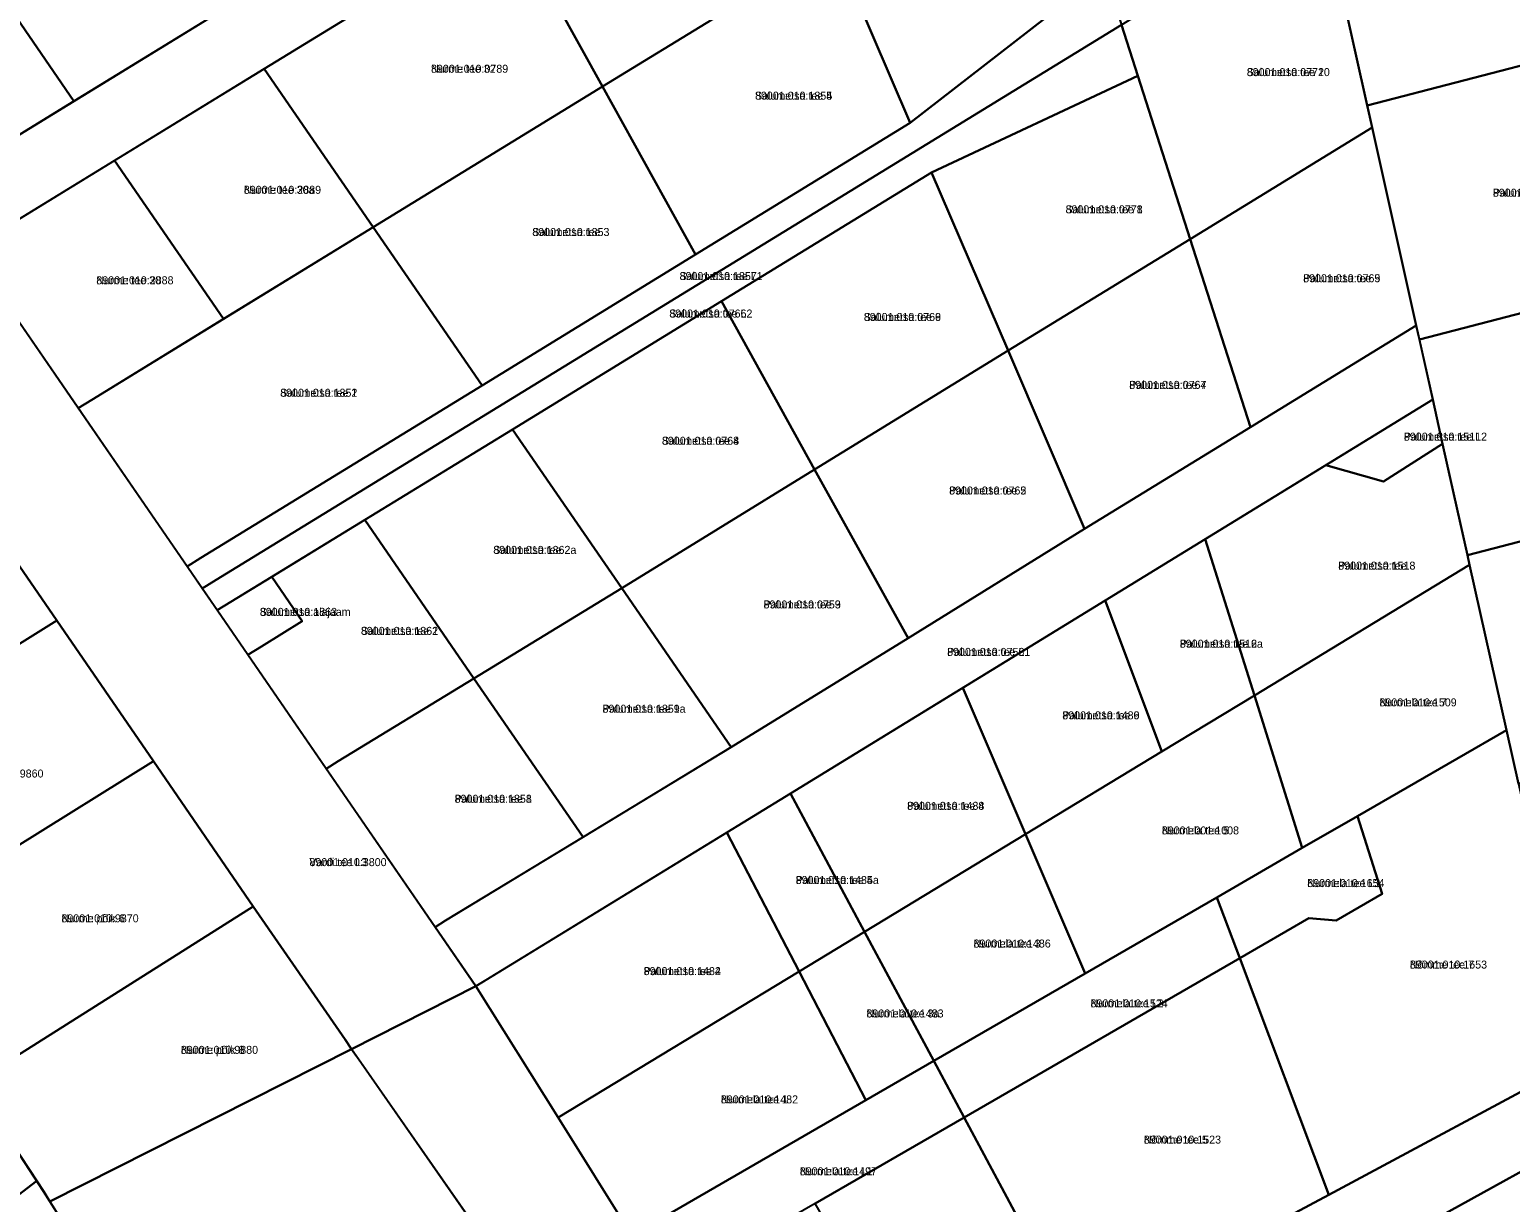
# Model space of a CAD drawing. Extents: x 526849 to 562296, y 6591741 to 6618546.
# Drawn here: x 546246.1 to 546524.3, y 6598599.5 to 6598819.9 of the extents above; entities that cross this region are included whole.
import ezdxf

# ---------------------------------------------------------------- set-up
doc = ezdxf.new("R2010")
doc.units = 0
for name, color, linetype in [('L_AADRESS', 7, 'Continuous'), ('PIIR', 7, 'Continuous'), ('TUNNUS', 7, 'Continuous')]:
    doc.layers.add(name, color=color, linetype=linetype)

msp = doc.modelspace()

# ---------------------------------------------------------------- linework, layer by layer
at = {"layer": 'PIIR'}
for points in [[(546227.01, 6598789.61), (546229.57, 6598791.18), (546282.53, 6598823.65), (546327.15, 6598851.02), (546371.97, 6598878.5), (546413.8, 6598904.15), (546446.52, 6598936.13), (546471.16, 6598923.58), (546475.1, 6598905.89), (546459.53, 6598913.79), (546427, 6598896.41), (546382.82, 6598869.32), (546336.26, 6598840.76), (546290.19, 6598812.52), (546237.29, 6598780.08), (546234.73, 6598778.51), (546230.83, 6598784.18)], [(546382.82, 6598869.32), (546397.2, 6598835.82), (546353.75, 6598809.17), (546336.26, 6598840.76)], [(546397.2, 6598835.82), (546438.34, 6598861.05), (546448.06, 6598830.75), (546411.59, 6598802.33)], [(546487.88, 6598848.56), (546523.89, 6598857.91), (546525.06, 6598853.05), (546534.16, 6598815.11), (546497.46, 6598805.58), (546488.92, 6598843.88)], [(546232.91, 6598837.74), (546260.42, 6598855.23), (546282.53, 6598823.65), (546254.4, 6598806.4)], [(546451.25, 6598820.78), (546488.92, 6598843.88), (546498.37, 6598801.48), (546464.17, 6598780.51), (546454.34, 6598811.15)], [(546290.19, 6598812.52), (546336.26, 6598840.76), (546353.75, 6598809.17), (546310.66, 6598782.75)], [(546205.45, 6598820.29), (546207.99, 6598821.9), (546232.91, 6598837.74), (546254.4, 6598806.4), (546229.57, 6598791.18), (546227.01, 6598789.61)], [(546353.75, 6598809.17), (546397.2, 6598835.82), (546411.59, 6598802.33), (546371.23, 6598777.58)], [(546275.68, 6598718.99), (546278.28, 6598720.58), (546331.14, 6598752.99), (546371.23, 6598777.58), (546411.59, 6598802.33), (546448.06, 6598830.75), (546451.25, 6598820.78), (546281.13, 6598716.46), (546278.52, 6598714.86)], [(546278.52, 6598714.86), (546281.13, 6598716.46), (546451.25, 6598820.78), (546454.34, 6598811.15), (546415.57, 6598793.04), (546376.08, 6598768.82), (546336.81, 6598744.74), (546283.93, 6598712.31), (546281.35, 6598710.73)], [(546497.46, 6598805.58), (546534.16, 6598815.11), (546543.5, 6598776.21), (546544.67, 6598771.35), (546507.25, 6598761.63), (546506.66, 6598764.26), (546498.37, 6598801.48)], [(546262.06, 6598795.27), (546290.19, 6598812.52), (546310.66, 6598782.75), (546282.53, 6598765.5)], [(546415.57, 6598793.04), (546454.34, 6598811.15), (546464.17, 6598780.51), (546429.96, 6598759.54)], [(546310.66, 6598782.75), (546353.75, 6598809.17), (546371.23, 6598777.58), (546331.14, 6598752.99)], [(546464.17, 6598780.51), (546498.37, 6598801.48), (546506.66, 6598764.26), (546475.5, 6598745.16)], [(546234.73, 6598778.51), (546237.29, 6598780.08), (546262.06, 6598795.27), (546282.53, 6598765.5), (546257.76, 6598750.31), (546255.2, 6598748.75)], [(546376.08, 6598768.82), (546415.57, 6598793.04), (546429.96, 6598759.54), (546393.6, 6598737.17)], [(546255.2, 6598748.75), (546257.76, 6598750.31), (546310.66, 6598782.75), (546331.14, 6598752.99), (546278.28, 6598720.58), (546275.68, 6598718.99)], [(546429.96, 6598759.54), (546464.17, 6598780.51), (546475.5, 6598745.16), (546444.34, 6598726.05)], [(546507.25, 6598761.63), (546544.67, 6598771.35), (546545.83, 6598766.48), (546554.35, 6598730.98), (546516.28, 6598721.1), (546514.43, 6598729.4), (546511.62, 6598742.01), (546509.77, 6598750.33)], [(546336.81, 6598744.74), (546376.08, 6598768.82), (546393.6, 6598737.17), (546357.36, 6598714.87)], [(546322.3, 6598651.21), (546324.27, 6598652.41), (546377.91, 6598685), (546411.16, 6598705.47), (546444.34, 6598726.05), (546475.5, 6598745.16), (546506.66, 6598764.26), (546509.77, 6598750.33), (546448.21, 6598712.58), (546389.08, 6598676.33), (546331.81, 6598641.21), (546329.96, 6598640.07)], [(546393.6, 6598737.17), (546429.96, 6598759.54), (546444.34, 6598726.05), (546411.16, 6598705.47)], [(546489.66, 6598738), (546509.77, 6598750.33), (546511.62, 6598742.01), (546500.53, 6598734.92)], [(546309.08, 6598727.74), (546336.81, 6598744.74), (546357.36, 6598714.87), (546329.59, 6598697.92)], [(546467, 6598724.11), (546489.66, 6598738), (546500.53, 6598734.92), (546511.62, 6598742.01), (546516.28, 6598721.1), (546516.68, 6598719.28), (546476.24, 6598694.75)], [(546357.36, 6598714.87), (546393.6, 6598737.17), (546411.16, 6598705.47), (546377.91, 6598685)], [(546201.21, 6598715.36), (546204.6, 6598717.48), (546232.99, 6598735.27), (546251.19, 6598708.83), (546218.96, 6598688.7)], [(546516.28, 6598721.1), (546554.35, 6598730.98), (546563.46, 6598693.05), (546564.62, 6598688.19), (546525.85, 6598678.12), (546523.6, 6598688.23), (546516.68, 6598719.28)], [(546287.11, 6598702.36), (546289.66, 6598703.94), (546297.33, 6598708.68), (546291.6, 6598717.02), (546309.08, 6598727.74), (546329.59, 6598697.92), (546304.1, 6598682.36), (546301.83, 6598680.97)], [(546448.21, 6598712.58), (546467, 6598724.11), (546476.24, 6598694.75), (546458.87, 6598684.21)], [(546476.24, 6598694.75), (546516.68, 6598719.28), (546523.6, 6598688.23), (546495.64, 6598672.07), (546485.25, 6598666.08)], [(546281.35, 6598710.73), (546283.93, 6598712.31), (546291.6, 6598717.02), (546297.33, 6598708.68), (546289.66, 6598703.94), (546287.11, 6598702.36)], [(546329.59, 6598697.92), (546357.36, 6598714.87), (546377.91, 6598685), (546350.1, 6598668.1)], [(546421.44, 6598696.16), (546448.21, 6598712.58), (546458.87, 6598684.21), (546433.22, 6598668.66)], [(546199.52, 6598676.55), (546251.19, 6598708.83), (546269.38, 6598682.37), (546217.07, 6598649.79)], [(546301.83, 6598680.97), (546304.1, 6598682.36), (546329.59, 6598697.92), (546350.1, 6598668.1), (546324.27, 6598652.41), (546322.3, 6598651.21)], [(546389.08, 6598676.33), (546421.44, 6598696.16), (546433.22, 6598668.66), (546403, 6598650.33)], [(546469.18, 6598656.79), (546444.44, 6598642.48), (546433.22, 6598668.66), (546458.87, 6598684.21), (546476.24, 6598694.75), (546485.25, 6598666.08)], [(546473.49, 6598645.37), (546486.48, 6598652.9), (546491.6, 6598652.43), (546500.25, 6598657.44), (546495.64, 6598672.07), (546523.6, 6598688.23), (546525.85, 6598678.12), (546537.42, 6598626.18), (546490.21, 6598600.91)], [(546217.07, 6598649.79), (546269.38, 6598682.37), (546288.13, 6598655.1), (546235.42, 6598621.83)], [(546377.09, 6598668.97), (546389.08, 6598676.33), (546403, 6598650.33), (546390.68, 6598642.86)], [(546469.18, 6598656.79), (546485.25, 6598666.08), (546495.64, 6598672.07), (546500.25, 6598657.44), (546491.6, 6598652.43), (546486.48, 6598652.9), (546473.49, 6598645.37)], [(546329.96, 6598640.07), (546377.09, 6598668.97), (546390.68, 6598642.86), (546345.4, 6598615.39)], [(546403, 6598650.33), (546433.22, 6598668.66), (546444.44, 6598642.48), (546416.01, 6598626.06)], [(546416.01, 6598626.06), (546444.44, 6598642.48), (546469.18, 6598656.79), (546473.49, 6598645.37), (546421.69, 6598615.44)], [(546248.72, 6598601.48), (546235.42, 6598621.83), (546288.13, 6598655.1), (546305.36, 6598630.05), (546306.59, 6598628.27), (546249.9, 6598599.66)], [(546390.68, 6598642.86), (546403, 6598650.33), (546416.01, 6598626.06), (546403.25, 6598618.69)], [(546421.69, 6598615.44), (546473.49, 6598645.37), (546490.21, 6598600.91), (546443.01, 6598575.64)], [(546345.4, 6598615.39), (546390.68, 6598642.86), (546403.25, 6598618.69), (546359.25, 6598593.27)], [(546249.9, 6598599.66), (546306.59, 6598628.27), (546308.31, 6598625.81), (546330.28, 6598594.29), (546276.64, 6598565.37), (546272.94, 6598563.37), (546264.35, 6598576.9)], [(546359.25, 6598593.27), (546403.25, 6598618.69), (546416.01, 6598626.06), (546421.69, 6598615.44), (546393.69, 6598599.27), (546370.98, 6598586.14), (546365.64, 6598583.06)], [(546195.44, 6598591.91), (546235.39, 6598621.82), (546247.42, 6598603.5), (546207.88, 6598573.16)], [(546393.69, 6598599.27), (546421.69, 6598615.44), (546443.01, 6598575.64), (546415.78, 6598561.05)], [(546508.58, 6598595.44), (546540.36, 6598613), (546543.44, 6598599.17)], [(546207.88, 6598573.16), (546247.42, 6598603.5), (546248.74, 6598601.5), (546249.9, 6598599.66), (546259.24, 6598584.94), (546257.16, 6598582.79), (546224.23, 6598548.61), (546209.82, 6598570.25)]]:
    msp.add_lwpolyline(points, close=True, dxfattribs=at)
for points in [[(546230.83, 6598784.18), (546329.96, 6598640.07), (546306.59, 6598628.27), (546305.36, 6598630.05), (546288.13, 6598655.1), (546269.38, 6598682.37), (546251.19, 6598708.83), (546232.99, 6598735.27)], [(546330.28, 6598594.29), (546306.59, 6598628.27), (546329.96, 6598640.07), (546345.4, 6598615.39), (546359.25, 6598593.27)], [(546443.01, 6598575.64), (546490.21, 6598600.91), (546537.42, 6598626.18)], [(546540.36, 6598613), (546508.58, 6598595.44)]]:
    msp.add_lwpolyline(points, dxfattribs=at)

# ---------------------------------------------------------------- texts
at = {"layer": 'L_AADRESS'}
for s, p in [('Nurme tee 32', (546321.52, 6598811.76)), ('Salumetsa tee 10', (546474.81, 6598811.13)), ('Salumetsa tee 5', (546382.41, 6598806.7)), ('Nurme tee 30a', (546286.36, 6598789.01)), ('Palumetsa tee 11', (546521.07, 6598788.46)), ('Salumetsa tee 8', (546440.75, 6598785.34)), ('Salumetsa tee 3', (546340.55, 6598781.08)), ('Nurme tee 30', (546258.63, 6598772.01)), ('Salumetsa tee L1', (546368.23, 6598772.8)), ('Palumetsa tee 9', (546485.41, 6598772.39)), ('Salumetsa tee L2', (546366.3, 6598765.76)), ('Salumetsa tee 6', (546402.85, 6598765.11)), ('Palumetsa tee 7', (546452.73, 6598752.35)), ('Salumetsa tee 1', (546293.18, 6598750.87)), ('Salumetsa tee 4', (546364.91, 6598741.85)), ('Palumetsa tee L2', (546504.34, 6598742.62)), ('Palumetsa tee 5', (546418.88, 6598732.5)), ('Salumetsa tee 2a', (546333.22, 6598721.34)), ('Palumetsa tee 8', (546492, 6598718.38)), ('Palumetsa tee 3', (546384.01, 6598711.09)), ('Salumetsa alajaam', (546289.35, 6598709.69)), ('Salumetsa tee 2', (546308.35, 6598706.12)), ('Palumetsa tee 6a', (546462.23, 6598703.71)), ('Palumetsa tee L1', (546418.51, 6598702.17)), ('Palumetsa tee 1a', (546353.75, 6598691.49)), ('Nurmela tee 7', (546499.75, 6598692.68)), ('Palumetsa tee 6', (546440.15, 6598690.25)), ('Palumetsa tee 1', (546325.96, 6598674.57)), ('Palumetsa tee 4', (546410.99, 6598673.24)), ('Nurmela tee 5', (546458.85, 6598668.62)), ('Vardi tee L3', (546298.67, 6598662.66)), ('Palumetsa tee 4a', (546390.05, 6598659.3)), ('Nurmela tee L3', (546486.18, 6598658.72)), ('Nurme põik 6', (546252.08, 6598652.1)), ('Nurmela tee 3', (546423.47, 6598647.36)), ('Palumetsa tee 2', (546361.48, 6598642.18)), ('Nõmme tee 7', (546505.46, 6598643.41)), ('Nurmela tee L2', (546445.45, 6598636.12)), ('Nurmela tee 3a', (546403.34, 6598634.22)), ('Nurme põik 8', (546274.52, 6598627.38)), ('Nurmela tee 1', (546375.99, 6598618.07)), ('Nõmme tee 5', (546455.47, 6598610.51)), ('Nurmela tee L1', (546390.82, 6598604.56))]:
    msp.add_text(s, height=1.5, dxfattribs=at).set_placement(p)
at = {"layer": 'TUNNUS'}
for s, p in [('89001:010:0789', (546321.52, 6598811.76)), ('89001:010:0772', (546474.81, 6598811.13)), ('89001:010:1854', (546382.41, 6598806.7)), ('89001:010:2889', (546286.36, 6598789.01)), ('89001:010:2393', (546521.07, 6598788.46)), ('89001:010:0771', (546440.75, 6598785.34)), ('89001:010:1853', (546340.55, 6598781.08)), ('89001:010:2888', (546258.63, 6598772.01)), ('89001:010:1857', (546368.23, 6598772.8)), ('89001:010:0765', (546485.41, 6598772.39)), ('89001:010:0766', (546366.3, 6598765.76)), ('89001:010:0769', (546402.85, 6598765.11)), ('89001:010:0764', (546452.73, 6598752.35)), ('89001:010:1852', (546293.18, 6598750.87)), ('89001:010:0768', (546364.91, 6598741.85)), ('89001:010:1511', (546504.34, 6598742.62)), ('89001:010:0762', (546418.88, 6598732.5)), ('89001:010:1862', (546333.22, 6598721.34)), ('89001:010:1513', (546492, 6598718.38)), ('89001:010:0759', (546384.01, 6598711.09)), ('89001:010:1863', (546289.35, 6598709.69)), ('89001:010:1861', (546308.35, 6598706.12)), ('89001:010:1512', (546462.23, 6598703.71)), ('89001:010:0756', (546418.51, 6598702.17)), ('89001:010:1859', (546353.75, 6598691.49)), ('89001:010:1509', (546499.75, 6598692.68)), ('89001:010:1489', (546440.15, 6598690.25)), ('89001:010:9860', (546234.2, 6598679.31)), ('89001:010:1858', (546325.96, 6598674.57)), ('89001:010:1488', (546410.99, 6598673.24)), ('89001:001:1008', (546458.85, 6598668.62)), ('89001:010:3800', (546298.67, 6598662.66)), ('89001:010:1485', (546390.05, 6598659.3)), ('89001:010:1654', (546486.18, 6598658.72)), ('89001:010:9870', (546252.08, 6598652.1)), ('89001:010:1486', (546423.47, 6598647.36)), ('89001:010:1484', (546361.48, 6598642.18)), ('89001:010:1653', (546505.46, 6598643.41)), ('89001:010:1524', (546445.45, 6598636.12)), ('89001:010:1483', (546403.34, 6598634.22)), ('89001:010:9880', (546274.52, 6598627.38)), ('89001:010:1482', (546375.99, 6598618.07)), ('89001:010:1523', (546455.47, 6598610.51)), ('89001:010:1497', (546390.82, 6598604.56))]:
    msp.add_text(s, height=1.5, dxfattribs=at).set_placement(p)

doc.saveas('drawing.dxf')
